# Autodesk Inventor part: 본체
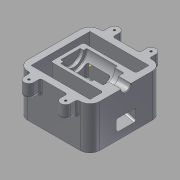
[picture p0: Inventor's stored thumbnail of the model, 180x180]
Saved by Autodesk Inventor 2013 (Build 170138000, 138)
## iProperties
Created: 2018-01
Part Number: 본체
Material: 알루미늄 6061
Document SubType Name: Modeling
Designer: Administrator
Density: 2.71 g/cm^3
Mass: 995.766 g
Surface Area: 840.611 cm^2
Volume: 367.441 cm^3
Author: Administrator
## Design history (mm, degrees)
sketch "스케치1"
  geometry: L1 (-55, 55)-(55, 55); L2 (55, 55)-(55, -55); L3 (55, -55)-(-55, -55); L4 (-55, -55)-(-55, 55); 3 further points
  constraints: 8 end point, 2 midpoint, 2 parallel, 1 horizontal, 1 horizontal alignment, 1 perpendicular, 1 vertical alignment
  dimensions: "d0" = 110 distance of L1.start L1.end; "d2" = 110 distance of L3.end L1.start
extrude "돌출1" new body sketch "스케치1" distance "d3" = 65; taper "d4" = 0 deg
sketch "스케치4"
  geometry: L1 (-55, 55)-(55, 55) reference; L2 (-20.5, 65.186)-(-20.5, 55); L3 (-35.5, 55)-(-35.5, 65.186); L4 (-35.5, 55)-(-20.5, 55); A1 r 7.5 centre (-28, 65.186) between (-20.5, 65.186) and (-35.5, 65.186); 1 further point
  constraints: 6 end point, 2 point on circle, 2 tangent, 1 centre point, 1 parallel, 1 point on line
  dimensions: "d11" = 15 diameter of A1; "d14" = 27 horizontal distance of L1.start A1.centre
extrude "돌출3" join sketch "스케치4" distance "d21" = 20; taper "d22" = 0 deg
sketch "스케치5"
  geometry: A1 r 7.5 centre (-28, -65.186) between (-35.5, -65.186) and (-20.5, -65.186) reference; A2 r 7.5 centre (28, -65.186) between (20.5, -65.186) and (35.5, -65.186) reference; A3 r 7.5 centre (28, 65.186) between (35.5, 65.186) and (20.5, 65.186) reference; A4 r 7.5 centre (-28, 65.186) between (-20.5, 65.186) and (-35.5, 65.186) reference; 5 further points
  constraints: 4 coincident
hole "구멍1" sketch "스케치5" at (-28, 65.186), (28, 65.186), (-28, -65.186), (28, -65.186) diameter "d26" = 3.242; stored, may be unused: countersink angle "d30" = 90 deg, drill point angle "d32" = 118 deg; dims "d27" = 9, "d28" = 4, "d29" = 2, "d31" = 11
sketch "스케치9"
  geometry: 1 further point
sketch "스케치10"
  geometry: L1 (-55, -65)-(-55, 0) reference; L2 (-55, 0)-(55, 0) reference; L3 (55, 0)-(55, -65) reference; L4 (55, -65)-(-55, -65) reference; L5 (-45, -65)-(-45, -56.436); L6 (-45, -56.436)-(35, -35); L7 (35, -35)-(35, 0); L8 (45, 0)-(45, -65); 1 further point
  constraints: 8 end point, 4 point on line, 2 perpendicular, 1 parallel
  dimensions: "d56" = 10 distance between parallel lines of L1 L5; "d57" = 105 deg angle of L6 L5; "d58" = 30 distance from line of L4 L6.end; "d59" = 10 distance between parallel lines of L8 L7; "d60" = 10 distance between parallel lines of L3 L8
extrude "돌출5" cut sketch "스케치10" stored distance "d61" = 90; taper "d62" = 0 deg
sketch "스케치11"
  geometry: L1 (55, 0)-(55, -65) reference; L2 (55, -65)-(45, -65) reference; L3 (45, -65)-(45, 0) reference; L4 (45, 0)-(55, 0) reference; L5 (-55, -65)-(-55, 0) reference; L6 (-55, 0)-(35, 0) reference; L7 (35, 0)-(35, -35) reference; L8 (35, -35)-(-45, -56.436) reference; L9 (-45, -56.436)-(-45, -65) reference; L10 (-45, -65)-(-55, -65) reference; L11 (-55, -7.5)-(-36, -7.5); L12 (-36, -7.5)-(-36, -16); L13 (-36, -16)-(-22, -16); L14 (-22, -16)-(-22, -20); L15 (-22, -20)-(25, -20); L16 (25, -20)-(25, -15); L17 (25, -15)-(30, -15); L18 (30, -15)-(30, 0); 1 further point
  constraints: 16 end point, 5 parallel, 3 perpendicular, 2 point on line
  dimensions: "d63" = 15 diameter of L11 L6; "d64" = 32 diameter of L13 L6; "d65" = 40 diameter of L15 L6; "d66" = 30 diameter of L17 L6; "d67" = 19 distance of L11.start L11.end; "d68" = 14 distance of L12.end L13.end; "d69" = 47 distance of L14.end L15.end; "d70" = 5 distance of L16.end L17.end
revolve "회전1" sketch "스케치11" stored, may be unused: angle "d71" = 90 deg
sketch "스케치13"
  geometry: L1 (-55, -35.939)-(-17, -25.757); L2 (45, 0)-(55, 0) reference; L3 (55, 0)-(55, -65) reference; L4 (55, -65)-(45, -65) reference; L5 (45, -65)-(45, 0) reference; L6 (-45, -56.436)-(-45, -65) reference; L7 (-45, -65)-(-55, -65) reference; L8 (-55, -65)-(-55, -7.5) reference; L9 (-55, -7.5)-(-36, -7.5) reference; L10 (-36, -7.5)-(-36, -16) reference; L11 (-36, -16)-(-22, -16) reference; L12 (-22, -16)-(-22, -20) reference; L13 (-22, -20)-(25, -20) reference; L14 (25, -20)-(25, -15) reference; L15 (25, -15)-(30, -15) reference; L16 (30, -15)-(30, 0) reference; L17 (30, 0)-(35, 0) reference; L18 (35, 0)-(35, -35) reference; L19 (35, -35)-(-45, -56.436) reference; L20 (20, -33.843)-(-55, -53.939); L21 (20, -33.843)-(20, -13.281); L22 (20, -13.281)-(-17, -13.281); L23 (-17, -13.281)-(-17, -25.757); L24 (-22, 0)-(-22, -16) reference; 1 further point
  constraints: 10 end point, 5 parallel, 2 point on line
  dimensions: "d77" = 18 distance of L20.end L1.start; "d121" = 5 distance between parallel lines of L19 L20; "d122" = 37 distance of L21.end L22.end; "d125" = 20.56234 distance of L20.start L21.end; "d126" = 5 distance from line of L22.end L24
extrude "돌출6" cut sketch "스케치13" stored distance "d80" = 30; taper "d81" = 0 deg
sketch "스케치14"
  geometry: L1 (55, -7.5)-(36, -7.5) reference; L2 (36, -7.5)-(36, -16) reference; L3 (-20.5, 55)-(20.5, 55) reference; L4 (20.5, -55)-(-20.5, -55) reference; L5 (-35, 45)-(-35, -45) reference; L6 (45, -25)-(-35, -25); L7 (45, 25)-(-35, 25); L8 (45, 45)-(-35, 45); L9 (45, -45)-(-35, -45); L10 (-35, -44.481)-(-35, -25); L11 (-35, 25)-(-35, 45); L12 (45, -45)-(45, -25); L13 (55, -7.5)-(55, -55) reference; L14 (45, 25)-(45, 45); L15 (55, 55)-(55, 7.5) reference; 1 further point
  constraints: 16 end point, 5 point on line, 4 parallel, 2 perpendicular
  dimensions: "d82" = 50 distance between parallel lines of L7 L6; "d83" = 25 distance from line of L6 point (0, 0); "d85" = 10 distance between parallel lines of L3 L8; "d86" = 10 distance between parallel lines of L4 L9; "d87" = 10 distance between parallel lines of L13 L12; "d88" = 10 distance between parallel lines of L15 L14
extrude "돌출7" cut sketch "스케치14" distance "d89" = 124.75; taper "d90" = 0 deg
fillet "모깎기2" dims "d93" = 3
fillet "모깎기3" dims "d94" = 3
chamfer "모따기1" distance "d95" = 1; stored, may be unused: second distance "d96" = 2, angle "d97" = 45 deg
fillet "모깎기5" dims "d99" = 1
fillet "모깎기8" dims "d127" = 3
fillet "모깎기9" dims "d128" = 15
fillet "모깎기12" dims "d131" = 3
fillet "모깎기13" dims "d132" = 3
node "작업 평면1"
sketch "스케치19" dims "d0" = 110, "d2" = 110
  geometry: L1 (72.5, 0)-(72.5, 65) reference; L2 (57.5, 65)-(72.5, 65) reference; 2 further points
  constraints: 1 other
  dimensions: "d136" = 55 distance from line of L1 point (17.5, 45); "d137" = 20 distance from line of L2 point (17.5, 45)
feature "엠보싱1" sketch "스케치19" dims "d0" = 110, "d2" = 110, "d138" = 0.5, "d139" = 0
node "솔리드1"
pattern_linear "직사각형 패턴1" dims "d25" = 56
mirror "대칭1"
node "절단 모서리 투영3"
node "절단 모서리 투영4"
node "절단 모서리 투영5"
other parameters: "d135" = 123
